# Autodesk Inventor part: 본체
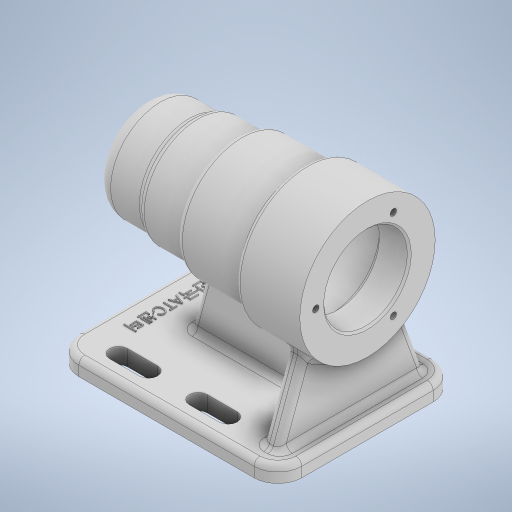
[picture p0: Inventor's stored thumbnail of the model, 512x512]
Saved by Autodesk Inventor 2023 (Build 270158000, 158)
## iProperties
Created: 2022-07
Part Number: 본체
Material: 일반
Document SubType Name: Modeling
Designer: owner
Density: 1 g/cm^3
Appearance: 기본값
Author: owner
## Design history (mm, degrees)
sketch "스케치1"
  geometry: L1 (-44, 45)-(44, 45); L2 (56, 33)-(56, -33); L3 (44, -45)-(-44, -45); L4 (-56, -33)-(-56, 33); L5 (56, 45)-(-56, -45); L6 (56, 0)-(-56, 0); L7 (0, -45)-(0, 45); A1 r 12 centre (44, -33) between (44, -45) and (56, -33); A2 r 12 centre (44, 33) between (56, 33) and (44, 45); A3 r 12 centre (-44, 33) between (-44, 45) and (-56, 33); A4 r 12 centre (-44, -33) between (-56, -33) and (-44, -45); 1 further point
  constraints: 14 end point, 8 point on circle, 8 tangent, 5 midpoint, 4 centre point, 4 point on line, 3 equal radius, 2 parallel, 1 horizontal, 1 perpendicular
  dimensions: "d2" = 12 radius of A1; "d15" = 112 distance between parallel lines of L4 L2; "d16" = 90 distance between parallel lines of L1 L3
extrude "돌출1" new body sketch "스케치1" distance "d17" = 8; taper "d18" = 0 deg
sketch "스케치2"
  geometry: L1 (-32, 87)-(-32, 89); L2 (-32, 89)-(-10, 89); L3 (-10, 89)-(-10, 92); L4 (-10, 92)-(24, 92); L5 (24, 92)-(24, 96); L6 (24, 96)-(56, 96); L7 (56, 96)-(56, 83); L8 (56, 83)-(41, 83); L9 (41, 83)-(41, 83); L10 (38, 86)-(-10, 86); L11 (-13, 83)-(-13, 83); L12 (-13, 83)-(-24.7, 83); L13 (-25, 82.7)-(-25, 79.5); L14 (-25, 79.5)-(-42.7, 79.5); L15 (-43, 79.2)-(-43, 78); L16 (-56, 62)-(56, 62); L17 (-32, 87)-(-56, 87); L18 (-56, 87)-(-56, 62); L19 (-44, 0)-(44, 0) reference; L20 (56, 0)-(56, -8) reference; L21 (-56, 62)-(-50, 62); L22 (-43, 78)-(-46.7, 78); L23 (-47, 77.7)-(-47, 72.5); L24 (-47, 72.5)-(-47, 72.5); L25 (-50, 69.5)-(-50, 62); A1 r 3 centre (38, 83) between (41, 83) and (38, 86); A2 r 3 centre (-10, 83) between (-10, 86) and (-13, 83); A3 r 0.3 centre (-24.7, 82.7) between (-24.7, 83) and (-25, 82.7); A4 r 0.3 centre (-42.7, 79.2) between (-42.7, 79.5) and (-43, 79.2); A5 r 0.3 centre (-46.7, 77.7) between (-46.7, 78) and (-47, 77.7); A6 r 3 centre (-47, 69.5) between (-47, 72.5) and (-50, 69.5); 7 further points
  constraints: 46 end point, 16 perpendicular, 15 point on line, 12 point on circle, 12 tangent, 6 centre point, 3 horizontal, 2 equal radius, 1 collinear, 1 vertical
  dimensions: "d19" = 15 distance between parallel lines of L7 L9; "d20" = 54 distance between parallel lines of L9 L11; "d21" = 12 distance between parallel lines of L11 L13; "d22" = 18 distance between parallel lines of L13 L15; "d25" = 34 distance between parallel lines of L6 L16; "d26" = 24 distance between parallel lines of L10 L16; "d27" = 21 distance between parallel lines of L8 L16; "d30" = 17.5 distance between parallel lines of L14 L16; "d32" = 27 distance between parallel lines of L2 L16; "d33" = 30 distance between parallel lines of L16 L4; "d35" = 112 distance between parallel lines of L7 L18; "d36" = 80 distance between parallel lines of L18 L5; "d37" = 46 distance between parallel lines of L18 L3; "d38" = 24 distance between parallel lines of L18 L1; "d39" = 62 distance between parallel lines of L16 L19; "d40" = 25 distance between parallel lines of L16 L17; "d41" = 3 radius of A1; "d42" = 0.3 radius of A3; "d49" = 4 distance of L15.end point (-47, 78); "d50" = 3 distance of L23.end point (-50, 72.5); "d51" = 16 distance between parallel lines of L16 L22; "d52" = 10.5 distance between parallel lines of L16 L24; "d53" = 0.3 radius of A5 (derived); "d54" = 3 radius of A6
revolve "회전2" sketch "스케치2" stored, may be unused: angle "d55" = 90 deg
sketch "스케치5" dims "d64" = 52
  geometry: L1 (0, 0)-(17, 29.445); L2 (0, 0)-(0, 34); C1 r 7.5 at (0, 0) reference; C2 r 21 at (0, 0) reference; 4 further points
  constraints: 4 end point, 1 coincident, 1 point on line, 1 vertical, 1 vertical alignment, 6 other
  dimensions: "d65" = 30 deg angle of L1 L2
hole "구멍1" sketch "스케치5" at (13, 22.517) diameter "d66" = 3.242; stored, may be unused: countersink angle "d70" = 90 deg, drill point angle "d72" = 118 deg; dims "d67" = 8, "d68" = 4, "d69" = 2, "d71" = 11
fillet "모깎기1" dims "d76" = 2
sketch "스케치6"
  geometry: L1 (-36, 33)-(-21, 33); L2 (-36, 28.5)-(-21, 28.5); L3 (-21, 37.5)-(-36, 37.5); L4 (-36, -33)-(-21, -33); L5 (-36, -37.5)-(-21, -37.5); L6 (-21, -28.5)-(-36, -28.5); L7 (-56, -33)-(-56, 33) reference; L8 (4, 33)-(19, 33); L9 (4, 28.5)-(19, 28.5); L10 (19, 37.5)-(4, 37.5); L11 (4, -33)-(19, -33); L12 (4, -37.5)-(19, -37.5); L13 (19, -28.5)-(4, -28.5); A1 r 4.5 centre (-36, 33) between (-36, 37.5) and (-36, 28.5); A2 r 4.5 centre (-21, 33) between (-21, 28.5) and (-21, 37.5); A3 r 4.5 centre (-36, -33) between (-36, -28.5) and (-36, -37.5); A4 r 4.5 centre (-21, -33) between (-21, -37.5) and (-21, -28.5); A5 r 4.5 centre (4, 33) between (4, 37.5) and (4, 28.5); A6 r 4.5 centre (19, 33) between (19, 28.5) and (19, 37.5); A7 r 4.5 centre (4, -33) between (4, -28.5) and (4, -37.5); A8 r 4.5 centre (19, -33) between (19, -37.5) and (19, -28.5); 5 further points
  constraints: 32 end point, 16 point on circle, 16 tangent, 8 centre point, 4 horizontal, 4 midpoint, 4 parallel
  dimensions: "d78" = 33 vertical distance of point (0, 0) point (-28.5, 33); "d79" = 33 vertical distance of point (-28.5, -33) point (0, 0); "d80" = 15 distance of L4.end L4.start; "d81" = 15 distance of L1.end L1.start; "d84" = 9 distance between parallel lines of L5 L6; "d85" = 9 distance between parallel lines of L2 L3; "d86" = 25 distance of L11.start L4.end; "d87" = 25 distance of L8.start L1.end; "d88" = 9 distance between parallel lines of L9 L10; "d89" = 9 distance between parallel lines of L12 L13; "d90" = 15 distance of L11.end L11.start; "d91" = 15 distance of L8.end L8.start; "d92" = 33 vertical distance of L8.start point (0, 0); "d93" = 33 vertical distance of L11.start point (0, 0); "d100" = 20 distance from line of L1.start L7; "d101" = 20 distance from line of L7 L4.start
extrude "돌출2" cut sketch "스케치6" distance "d94" = 10; taper "d95" = 0 deg
node "작업 평면1"
sketch "스케치10"
  geometry: L1 (0, 37.5)-(0, 28.5) reference; L2 (0, -33)-(0, 33) reference; L3 (0, -45)-(0, -33) reference; L4 (37.342, 23.409)-(0, 37); L5 (0, 45)-(-8, 45) reference; L6 (37.342, -23.409)-(0, -37); L7 (0, -45)-(-8, -45) reference; A1 r 34 centre (62, 0) between (37.342, 23.409) and (37.342, -23.409) reference; 1 further point
  constraints: 4 end point, 2 point on circle, 2 point on line, 1 midpoint
  dimensions: "d115" = 8 distance from line of L4.end L5; "d116" = 8 distance from line of L7 L6.end; "d117" = 110 deg angle of L6 L3; "d118" = 110 deg angle of L1 L4
extrude "돌출4" join sketch "스케치10" distance "d119" = 8; taper "d120" = 0 deg
sketch "스케치11"
  geometry: L1 (-29, 0)-(-19.279, 36.279); L2 (44, 0)-(-44, 0) reference; L3 (48, 0)-(48, 37.342) reference; L4 (40, 0)-(48, 0) reference; L5 (40, 37.342)-(40, 0) reference; L6 (48, 37.342)-(40, 37.342) reference; L7 (-19.279, 36.279)-(40, 36.279); 4 further points
  constraints: 4 end point, 3 point on line, 1 perpendicular
  dimensions: "d121" = 105 deg angle of L1 L2; "d122" = 77 distance of L3.start L1.start; "d142" = 59.27895 distance of L1.end L7.end
  node "투영된 루프1"
fillet "모깎기3" dims "d125" = 3
fillet "모깎기4" dims "d126" = 3
sketch "스케치12"
  geometry: L1 (-56, -33)-(-56, 33) reference; 2 further points
  constraints: 1 horizontal alignment, 1 other
  dimensions: "d127" = 12 distance from line of L1 point (-44, 0)
feature "엠보싱1" sketch "스케치12" dims "d19" = 15, "d20" = 54, "d21" = 12, "d22" = 18, "d25" = 34, "d26" = 24, "d27" = 21, "d30" = 17.5, "d32" = 27, "d33" = 30, "d35" = 112, "d36" = 80, "d37" = 46, "d38" = 24, "d39" = 62, "d40" = 25, "d41" = 3, "d42" = 0.3, "d49" = 4, "d50" = 3, "d51" = 16, "d52" = 10.5, "d53" = 0.3 (derived), "d54" = 3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
chamfer "모따기1" distance "d130" = 1; stored, may be unused: second distance "d131" = 2, angle "d132" = 45 deg
extrude "돌출6" join sketch "스케치11" stored distance "d134" = 8; taper "d135" = 0 deg
fillet "모깎기5" dims "d136" = 3
fillet "모깎기6" dims "d137" = 3
fillet "모깎기7" dims "d138" = 3
fillet "모깎기9" dims "d140" = 8
fillet "모깎기10" dims "d141" = 3
node "솔리드1"
pattern_circular "원형 패턴1" dims angle "d74" = 360 deg
feature "A9D066F2-1C7D-4E18-AEED-F7BC21143FA4" dims "d66" = 3.242, "d67" = 8, "d68" = 4, "d69" = 2, "d70" = 90 deg, "d71" = 11, "d72" = 118 deg
other parameters: "d110" = 48
